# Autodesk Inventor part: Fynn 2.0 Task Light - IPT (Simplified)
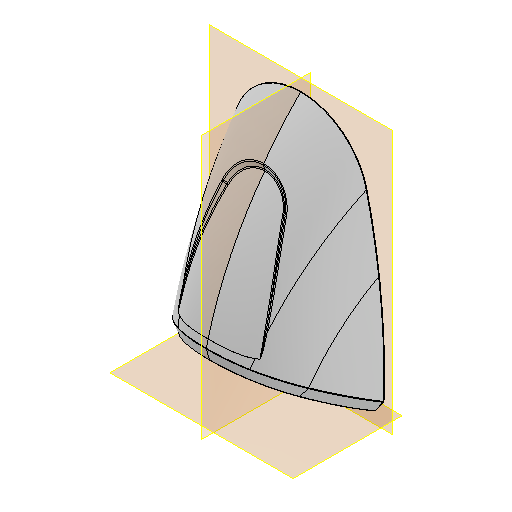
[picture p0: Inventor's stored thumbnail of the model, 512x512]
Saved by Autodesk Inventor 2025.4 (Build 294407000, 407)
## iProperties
Created: 2026-08
Part Number: Fynn 2.0 Task Light - IPT (Simplified)
Material: Generic
Description: STEP AP214
Document SubType Name: Modeling
Designer: Brian.Thangei
Density: 1 g/cm^3
Appearance: Default
Sending System: SolidWorks 2026
Preprocessor: SwSTEP 2.0
Title: 1293-A01-T2-BIM.STEP
Revision Number: ANY
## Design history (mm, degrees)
chamfer "Chamfer2"
chamfer "1293-A01-T2-BIM.SAT_1_[1]"
chamfer "1293-A01-T2-BIM.SAT_1_[2]"
workplane "Work Plane1"
node "Direct Edit1"
node "Direct Edit2"
mirror "Mirror1"
node "BACK PLATE"
node "BODY"
node "SCREW"
feature "Pattern of SCREW:1"
node "SCREW 2"
feature "Rotate1" dims "d0" = -6.1
move_body "Move1" dims "d1" = 0, "d3" = 92.075
move_body "Move2" dims "d4" = -39.688, "d6" = -6.35
move_body "Move3" dims "d8" = -44
move_body "Move4" dims "d12" = -6.35
move_body "Move5" dims "d13" = -0.5
move_body "Move6" dims "d16" = 0.25
other parameters: "d2" = 0, "d5" = 0, "d7" = 0, "d9" = 0, "d10" = 0, "d11" = 0, "d14" = 0, "d15" = 0, "d17" = 0, "d18" = 0
